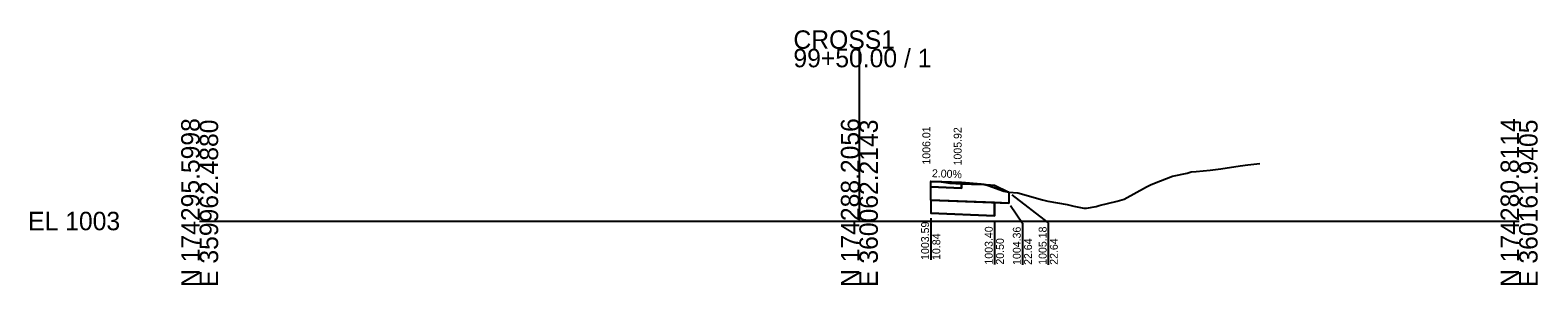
# Model space of a CAD drawing. Extents: x -26 to 1403, y -10 to 11027.
# Drawn here: x 1174.3 to 1402.8, y 2990.3 to 3029 of the extents above; entities that cross this region are included whole.
import ezdxf

# ---------------------------------------------------------------- set-up
doc = ezdxf.new("R2010")
doc.units = 0
for name, color, linetype in [('Default', 7, 'Continuous'), ('GSBWFILL', 7, 'Continuous'), ('GSCOLORFILL', 7, 'Continuous'), ('P_XS_EAR_CommonGrnd', 7, 'Continuous'), ('P_XS_Rock', 7, 'Continuous'), ('P_XS_Subgrade', 7, 'Continuous')]:
    doc.layers.add(name, color=color, linetype=linetype)

msp = doc.modelspace()

# ---------------------------------------------------------------- linework, layer by layer
at = {"layer": 'Default'}
for p, q in [((1300, 3000), (1300, 3026.14)), ((1200, 3000), (1300, 3000)), ((1300, 3000), (1400, 3000))]:
    msp.add_line(p, q, dxfattribs=at)
at = {"layer": 'GSBWFILL'}
for p, q in [((1310.84, 3006.02), (1315.5, 3005.84)), ((1315.5, 3005.84), (1320.5, 3005.44)), ((1320.5, 3005.44), (1322.64, 3004.37))]:
    msp.add_line(p, q, dxfattribs=at)
at = {"layer": 'GSCOLORFILL'}
for p, q in [((1310.84, 3005.19), (1310.84, 3006.02)), ((1315.5, 3005), (1315.5, 3005.84)), ((1310.84, 3005.19), (1315.5, 3005)), ((1310.84, 3003.19), (1310.84, 3005.19)), ((1310.84, 3003.19), (1322.64, 3002.72)), ((1310.84, 3003.19), (1310.84, 3001.19)), ((1322.64, 3004.37), (1322.64, 3002.72)), ((1320.5, 3000.8), (1310.84, 3001.19)), ((1320.5, 3002.8), (1320.5, 3000.8))]:
    msp.add_line(p, q, dxfattribs=at)
at = {"layer": 'P_XS_EAR_CommonGrnd'}
for points in [[(1310.84, 3006.02), (1312.45, 3005.97), (1312.52, 3005.96)], [(1313.7, 3005.73), (1315.5, 3005.66), (1315.5, 3005), (1310.84, 3005.19), (1310.84, 3006.02), (1312.52, 3005.96)], [(1322.64, 3004.37), (1322.64, 3002.72), (1320.5, 3002.8), (1310.84, 3003.19), (1310.84, 3005.19), (1315.5, 3005), (1315.5, 3005.66), (1315.97, 3005.64), (1316.99, 3005.6), (1317.45, 3005.61), (1318.48, 3005.6), (1318.92, 3005.56), (1319.51, 3005.39), (1321.92, 3004.55)], [(1313.7, 3005.73), (1315.5, 3005.66), (1315.5, 3005.84), (1312.52, 3005.96)], [(1315.97, 3005.64), (1316.99, 3005.6), (1317.45, 3005.61), (1318.48, 3005.6), (1315.5, 3005.84), (1315.5, 3005.66)], [(1318.82, 3005.59), (1318.92, 3005.56), (1318.48, 3005.6)], [(1318.92, 3005.56), (1320.5, 3005.44), (1322.64, 3004.37), (1321.92, 3004.55), (1319.51, 3005.39)], [(1310.84, 3003.19), (1310.84, 3001.19), (1320.5, 3000.8), (1320.5, 3002.8)]]:
    msp.add_lwpolyline(points, close=True, dxfattribs=at)
at = {"layer": 'P_XS_Rock'}
for p, q in [((1323.11, 3004), (1328.63, 2999.71)), ((1322.89, 3002.35), (1324.71, 2999.69)), ((1310.81, 3000.45), (1310.81, 2994.1)), ((1320.46, 2999.85), (1320.46, 2993.39)), ((1324.71, 2999.69), (1324.71, 2993.34)), ((1328.63, 2999.71), (1328.63, 2993.36))]:
    msp.add_line(p, q, dxfattribs=at)
at = {"layer": 'P_XS_Subgrade'}
for p, q in [((1350.28, 3007.46), (1351.03, 3007.51)), ((1351.03, 3007.51), (1353.19, 3007.72)), ((1353.19, 3007.72), (1354.8, 3007.91)), ((1354.8, 3007.91), (1357.73, 3008.36)), ((1357.73, 3008.36), (1358.86, 3008.55)), ((1358.86, 3008.55), (1360.71, 3008.71)), ((1310.75, 3006.03), (1312.45, 3005.97)), ((1312.45, 3005.97), (1313.7, 3005.73)), ((1313.7, 3005.73), (1315.97, 3005.64)), ((1315.97, 3005.64), (1316.99, 3005.6)), ((1316.99, 3005.6), (1317.45, 3005.61)), ((1317.45, 3005.61), (1318.82, 3005.59)), ((1318.82, 3005.59), (1319.51, 3005.39)), ((1319.51, 3005.39), (1321.92, 3004.55)), ((1343.5, 3005.2), (1344.12, 3005.52)), ((1344.12, 3005.52), (1344.73, 3005.75)), ((1344.73, 3005.75), (1347.47, 3006.82)), ((1347.47, 3006.82), (1349.69, 3007.28)), ((1349.69, 3007.28), (1350.28, 3007.46)), ((1321.92, 3004.55), (1322.64, 3004.37)), ((1322.64, 3004.37), (1324.04, 3004.27)), ((1324.04, 3004.27), (1327.74, 3003.22)), ((1327.74, 3003.22), (1328.54, 3003.03)), ((1328.54, 3003.03), (1331.51, 3002.5)), ((1336.34, 3002.36), (1339.09, 3003.03)), ((1339.09, 3003.03), (1340.11, 3003.34)), ((1340.11, 3003.34), (1343.5, 3005.2)), ((1331.51, 3002.5), (1332.52, 3002.26)), ((1332.52, 3002.26), (1334.02, 3001.97)), ((1334.02, 3001.97), (1334.44, 3001.95)), ((1334.44, 3001.95), (1335.89, 3002.23)), ((1335.89, 3002.23), (1336.34, 3002.36))]:
    msp.add_line(p, q, dxfattribs=at)

# ---------------------------------------------------------------- texts
at = {"layer": 'Default'}
for s, p in [('CROSS1', (1290, 3026.14)), ('99+50.00 / 1', (1290, 3023.34)), ('EL 1003', (1174, 2998.6))]:
    msp.add_text(s, height=2.8, dxfattribs=at).set_placement(p)
for s, p in [('N 174295.5998', (1200, 2990)), ('E 359962.4880', (1202.8, 2990)), ('N 174288.2056', (1300, 2990)), ('E 360062.2143', (1302.8, 2990)), ('N 174280.8114', (1400, 2990)), ('E 360161.9405', (1402.8, 2990))]:
    msp.add_text(s, height=2.8, rotation=90, dxfattribs=at).set_placement(p)
at = {"layer": 'P_XS_Rock'}
for s, rotation, p in [('1006.01', 90, (1310.75, 3008.57)), ('1005.92', 90, (1315.5, 3008.44)), ('2.00%', 357.7094, (1310.97, 3006.67)), ('1003.59', 90, (1310.56, 2994.1)), ('1003.40', 90, (1320.21, 2993.39)), ('1004.36', 90, (1324.46, 2993.34)), ('1005.18', 90, (1328.38, 2993.36)), ('10.84', 90, (1312.26, 2994.1)), ('20.50', 90, (1321.91, 2993.39)), ('22.64', 90, (1326.16, 2993.34)), ('22.64', 90, (1330.08, 2993.36))]:
    msp.add_text(s, height=1.2, rotation=rotation, dxfattribs=at).set_placement(p)

doc.saveas('drawing.dxf')
